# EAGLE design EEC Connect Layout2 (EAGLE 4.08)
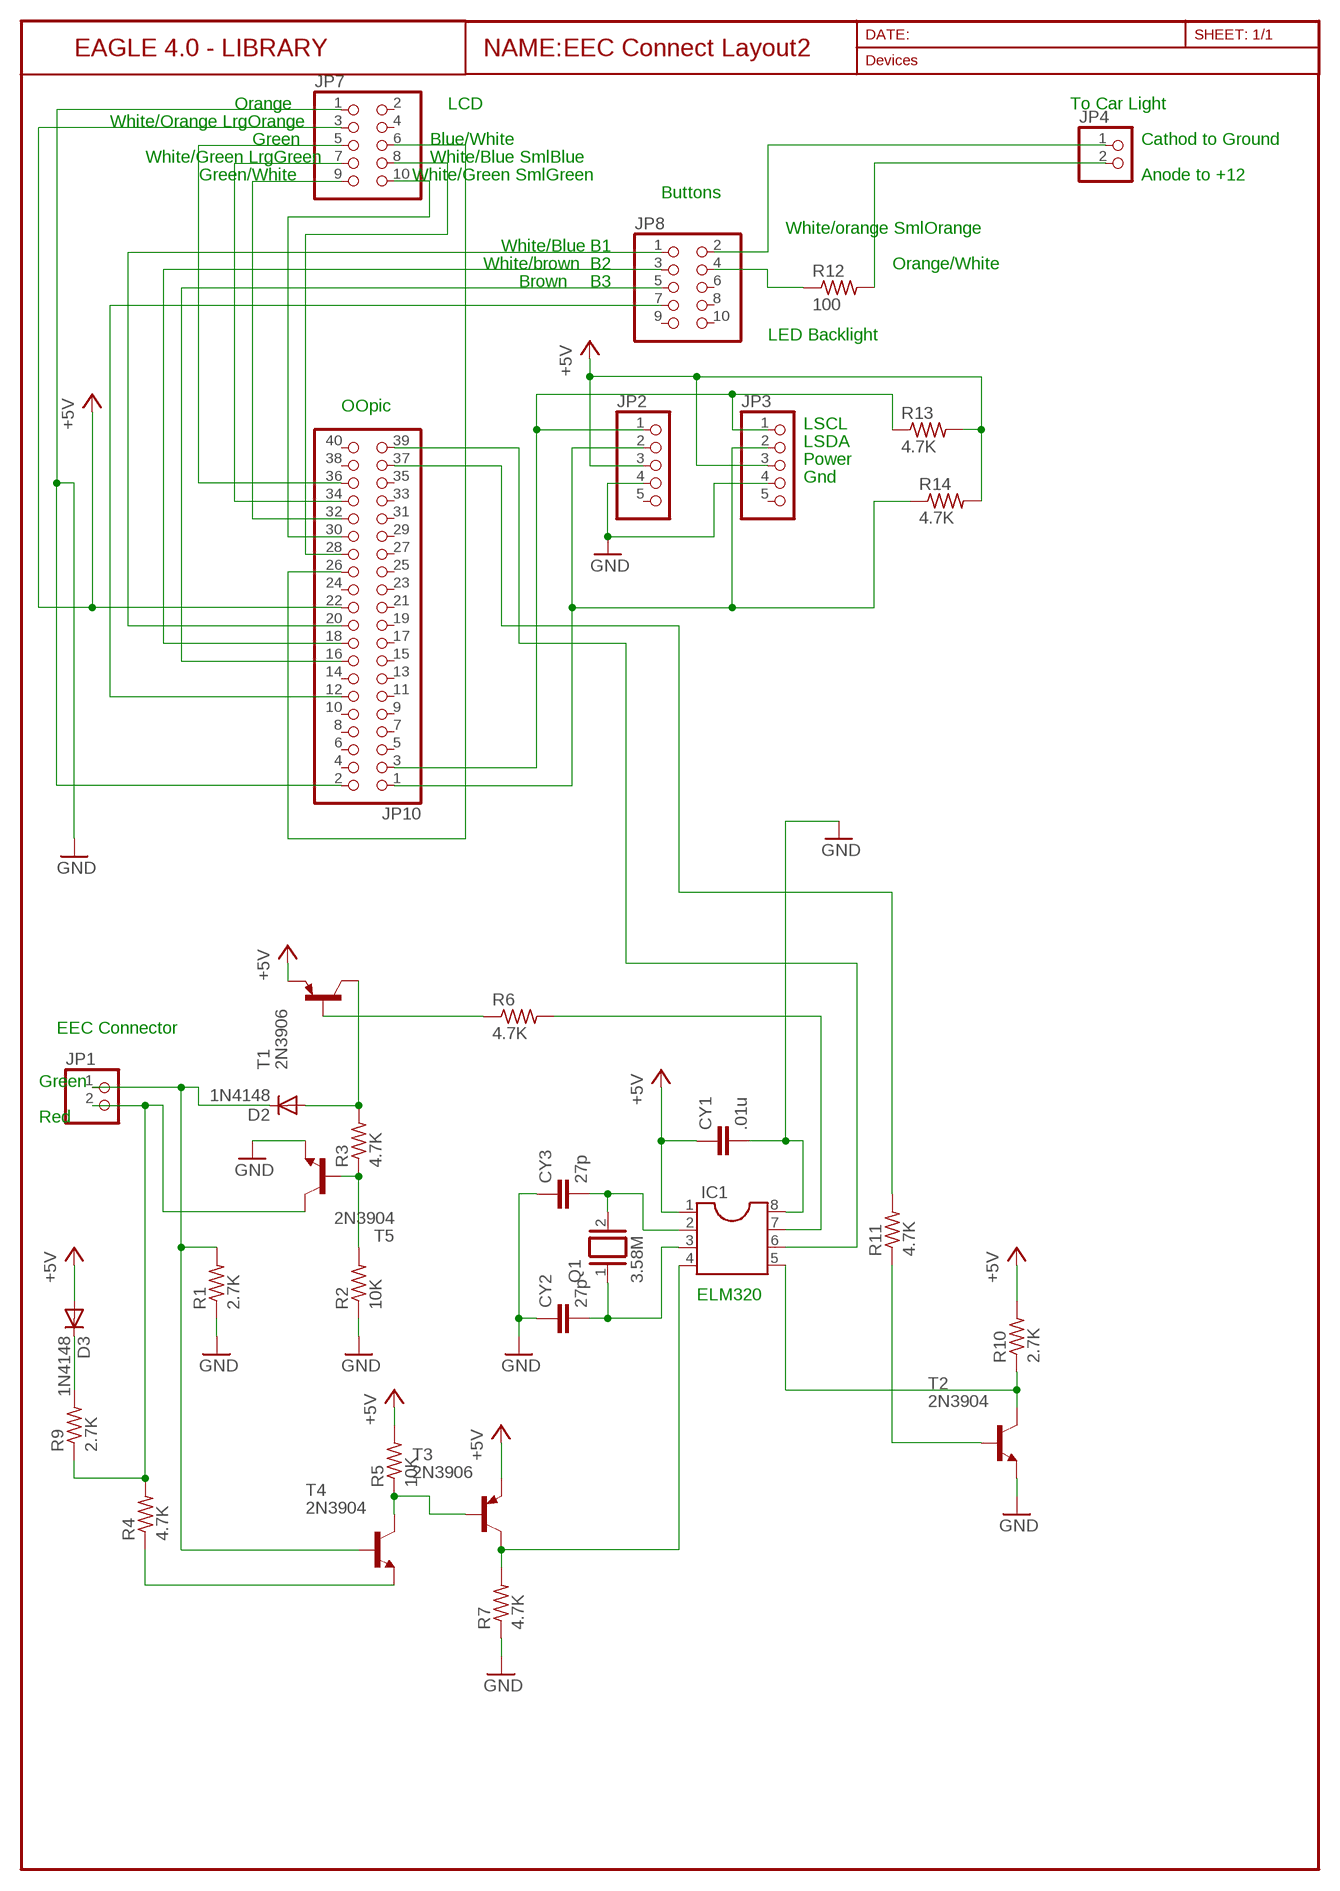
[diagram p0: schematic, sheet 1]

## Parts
CY1  .01u  CYYC7B5  [YC7B5]
CY2  27p  CYYC7B5  [YC7B5]
CY3  27p  CYYC7B5  [YC7B5]
D2  1N4148  [DO35-10]
D3  1N4148  [DO35-10]
IC1  DIL8  [DIL08]
JP1  PINHD-1X2  [1X02]
JP2  PINHD-1X5  [1X05]
JP3  PINHD-1X5  [1X05]
JP4  PINHD-1X2  [1X02]
JP7  PINHD-2X5  [2X05]
JP8  PINHD-2X5  [2X05]
JP10  PINHD-2X20  [2X20]
Q1  3.58M  XTAL/S  [QS]
R1  2.7K  R-US_0207/10  [0207/10]
R2  10K  R-US_0207/10  [0207/10]
R3  4.7K  R-US_0207/10  [0207/10]
R4  4.7K  R-US_0207/10  [0207/10]
R5  10K  R-US_0207/10  [0207/10]
R6  4.7K  R-US_0207/10  [0207/10]
R7  4.7K  R-US_0207/10  [0207/10]
R9  2.7K  R-US_0207/10  [0207/10]
R10  2.7K  R-US_0207/10  [0207/10]
R11  4.7K  R-US_0207/10  [0207/10]
R12  100  R-US_0204/7  [0204/7]
R13  4.7K  R-US_0204/7  [0204/7]
R14  4.7K  R-US_0204/7  [0204/7]
T1  2N3906  [TO92]
T2  2N3904  [TO92]
T3  2N3906  [TO92]
T4  2N3904  [TO92]
T5  2N3904  [TO92]

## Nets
+5V: CY1.1 D3.A IC1.1 JP2.3 JP3.3 JP7.3 JP10.22 R5.2 R10.2 R13.2 R14.2 T1.3(E) T3.3(E)
N$1: JP7.8 JP10.28
N$2: R2.2 R3.1 T5.2(B)
N$3: D2.C JP1.1 R1.2 T4.2(B)
N$4: IC1.4 R7.2 T3.1(C)
N$5: CY3.2 IC1.2 Q1.2
N$6: CY2.2 IC1.3 Q1.1
N$8: JP8.5 JP10.16
N$9: D3.C R9.2
N$10: R4.1 T4.3(E)
N$11: R5.1 T3.2(B) T4.1(C)
N$12: JP7.5 JP10.36
N$13: JP4.2 R12.2
N$15: IC1.7 R6.2
N$16: R6.1 T1.2(B)
N$17: D2.A R3.2 T1.1(C)
N$19: JP1.2 R4.2 R9.1 T5.1(C)
N$20: JP8.4 R12.1
N$21: IC1.6 JP10.39
N$22: JP7.10 JP10.30
N$23: JP4.1 JP8.2
N$24: JP2.1 JP3.1 JP10.3 R13.1
N$25: JP2.2 JP3.2 JP10.1 R14.1
N$26: JP7.6 JP10.26
N$27: JP8.7 JP10.12
N$30: JP8.1 JP10.20
N$31: JP8.3 JP10.18
N$32: CY1.2 CY2.1 CY3.1 IC1.8 JP2.4 JP3.4 JP7.1 JP10.2 R1.1 R2.1 R7.1 T2.3(E) T5.3(E) ; supply symbol labelled GND
N$34: JP7.9 JP10.32
N$35: JP7.7 JP10.34
N$36: R11.1 T2.2(B)
N$37: JP10.37 R11.2
N$40: IC1.5 R10.1 T2.1(C)
Unconnected: JP2.5 JP3.5 JP7.2 JP7.4 JP8.6 JP8.8 JP8.9 JP8.10 JP10.4 JP10.5 JP10.6 JP10.7 JP10.8 JP10.9 JP10.10 JP10.11 JP10.13 JP10.14 JP10.15 JP10.17 JP10.19 JP10.21 JP10.23 JP10.24 JP10.25 JP10.27 JP10.29 JP10.31 JP10.33 JP10.35 JP10.38 JP10.40

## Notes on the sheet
- Orange | LCD | To Car Light
- White/Orange LrgOrange
- Green | Blue/White | Cathod to Ground
- White/Green LrgGreen | White/Blue SmlBlue
- Green/White | White/Green SmlGreen | Anode to +12
- Buttons
- White/orange SmlOrange
- White/Blue | B1
- White/brown | B2 | Orange/White
- Brown | B3
- LED Backlight
- OOpic
- LSCL
- LSDA
- Power
- Gnd
- EEC Connector
- Green
- Red
- ELM320

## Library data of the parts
CY1-CY3 = rcl:CY: Y CAPACITOR
D2 D3 = diode:1N4148: DIODE
IC1 = dil:DIL8: SOCKET Dual In Line
JP1 JP4 = pinhead:PINHD-1X2: PIN HEADER
JP2 JP3 = pinhead:PINHD-1X5: PIN HEADER
JP7 JP8 = pinhead:PINHD-2X5: PIN HEADER
JP10 = pinhead:PINHD-2X20: PIN HEADER
Q1 = special:XTAL/S: CRYSTAL
R1-R7 R9-R14 = rcl:R-US_: RESISTOR, American symbol
T1 T3 = transistor-pnp:2N3906: PNP TRANSISTOR
T2 T4 T5 = transistor-npn:2N3904: NPN TRANSISTOR

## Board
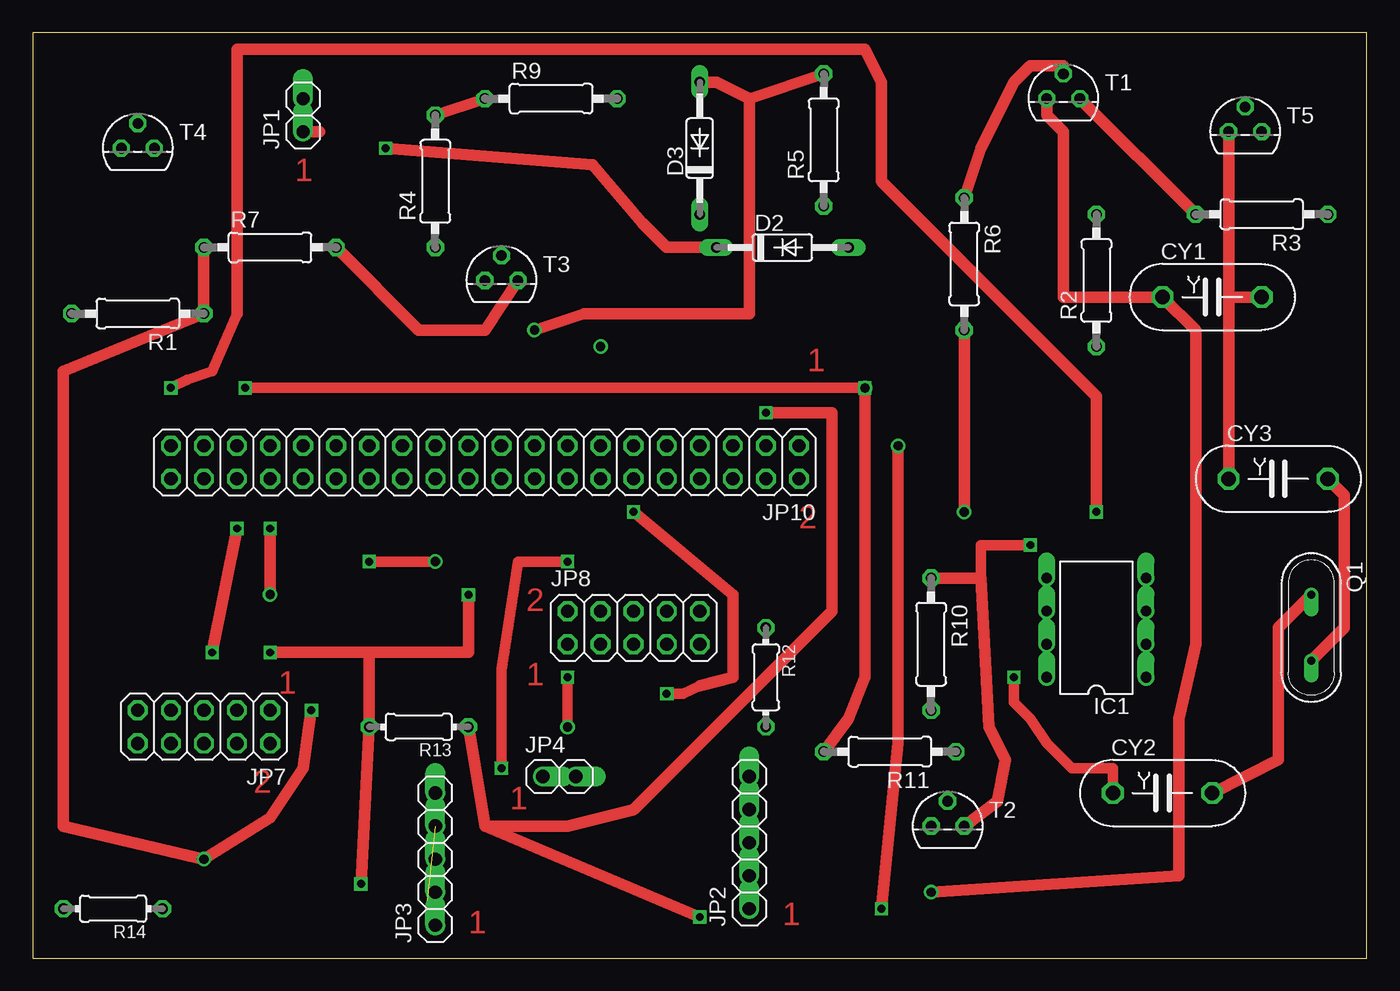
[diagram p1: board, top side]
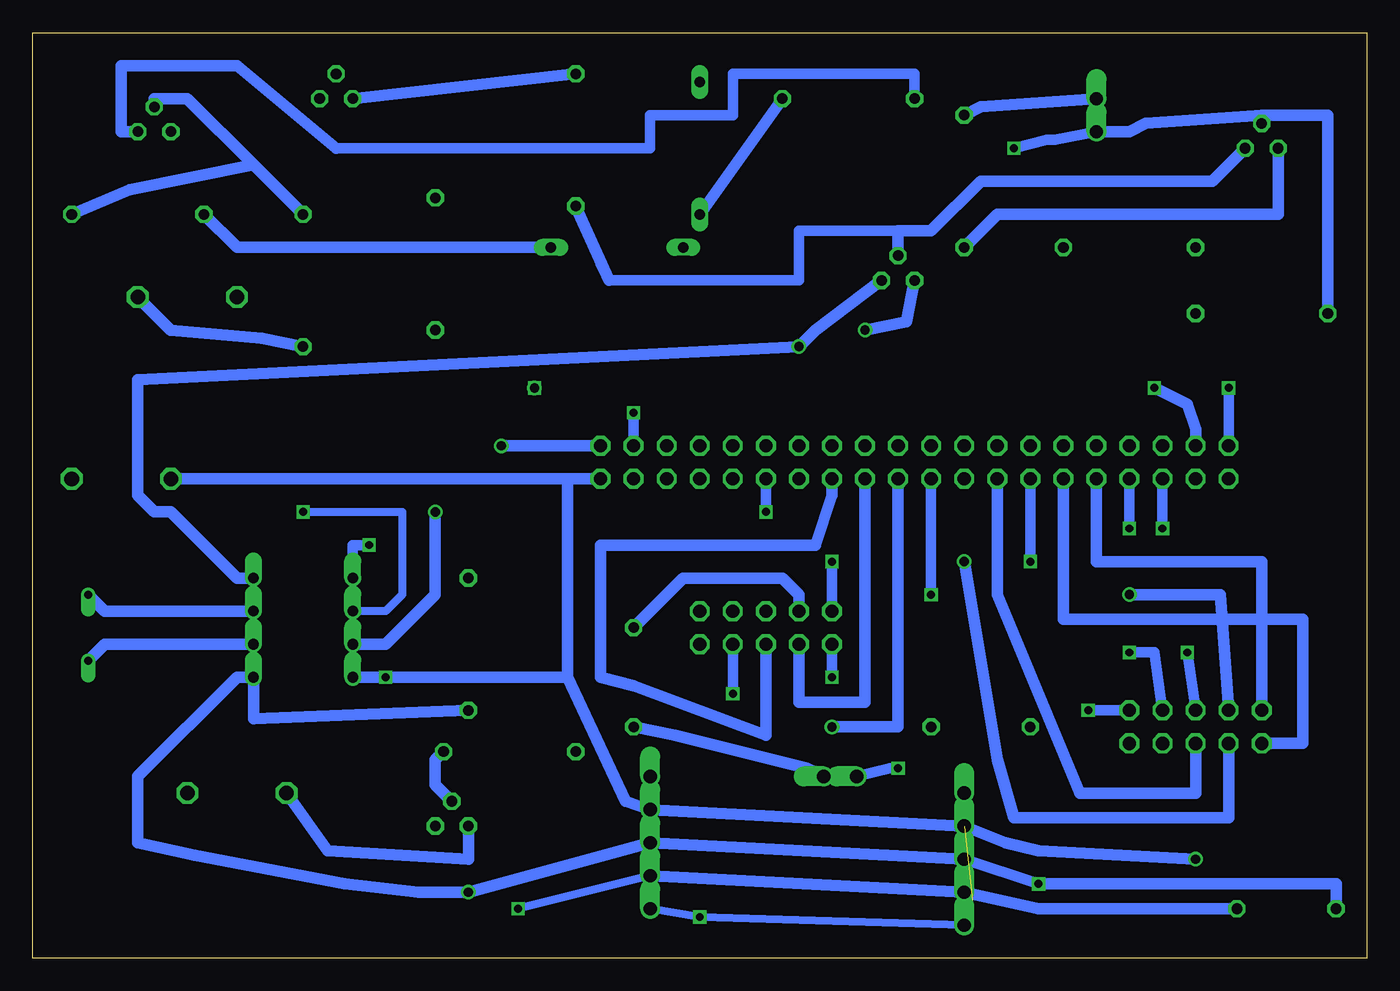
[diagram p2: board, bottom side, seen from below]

Size 102.54 x 71.11 mm. Coordinates in mm from the lower left corner, seen from the top.
Outline: 0,0 102.54,0 102.54,71.11 0,71.11 0,0
Copper layers used: Top, Bottom

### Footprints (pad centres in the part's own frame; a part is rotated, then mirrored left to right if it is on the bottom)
YC7B5 = drill 1.118 octagon: 1 -3.81,0; 2 3.81,0
DO35-10 = drill 0.813 long: A 5.08,0; C -5.08,0
DIL08 = drill 0.813 offset: 1 -3.81,-3.81; 2 -1.27,-3.81; 3 1.27,-3.81; 4 3.81,-3.81; 5 3.81,3.81; 6 1.27,3.81; 7 -1.27,3.81; 8 -3.81,3.81
1X02 = drill 1.016 offset: 1 -1.27,0; 2 1.27,0
1X05 = drill 1.016 offset: 1 -5.08,0; 2 -2.54,0; 3 0,0; 4 2.54,0; 5 5.08,0
2X05 = drill 1.016 octagon: 1 -5.08,-1.27; 2 -5.08,1.27; 3 -2.54,-1.27; 4 -2.54,1.27; 5 0,-1.27; 6 0,1.27; 7 2.54,-1.27; 8 2.54,1.27; 9 5.08,-1.27; 10 5.08,1.27
2X20 = drill 1.016 octagon: 1 -24.13,-1.27; 2 -24.13,1.27; 3 -21.59,-1.27; 4 -21.59,1.27; 5 -19.05,-1.27; 6 -19.05,1.27; 7 -16.51,-1.27; 8 -16.51,1.27; 9 -13.97,-1.27; 10 -13.97,1.27; 11 -11.43,-1.27; 12 -11.43,1.27; 13 -8.89,-1.27; 14 -8.89,1.27; 15 -6.35,-1.27; 16 -6.35,1.27; 17 -3.81,-1.27; 18 -3.81,1.27; 19 -1.27,-1.27; 20 -1.27,1.27; 21 1.27,-1.27; 22 1.27,1.27; 23 3.81,-1.27; 24 3.81,1.27; 25 6.35,-1.27; 26 6.35,1.27; 27 8.89,-1.27; 28 8.89,1.27; 29 11.43,-1.27; 30 11.43,1.27; 31 13.97,-1.27; 32 13.97,1.27; 33 16.51,-1.27; 34 16.51,1.27; 35 19.05,-1.27; 36 19.05,1.27; 37 21.59,-1.27; 38 21.59,1.27; 39 24.13,-1.27; 40 24.13,1.27
QS = drill 0.61 offset: 1 -2.54,0; 2 2.54,0
0207/10 = drill 0.813 octagon: 1 -5.08,0; 2 5.08,0
0204/7 = drill 0.813 octagon: 1 -3.81,0; 2 3.81,0
TO92 = drill 0.813 octagon: 1 1.27,0; 2 0,1.905; 3 -1.27,0

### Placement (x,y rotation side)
CY1  90.64,50.8 0 top
CY2  86.83,12.7 0 top
CY3  95.72,36.82 0 top
D2  57.62,54.6 0 top
D3  51.27,62.23 90 top
IC1  81.75,25.39 90 top
JP1  20.79,64.77 90 top
JP2  55.08,8.89 90 top
JP3  30.95,7.61 90 top
JP4  40.48,13.96 0 top
JP7  13.17,17.77 180 top
JP8  46.19,25.39 0 top
JP10  34.76,38.09 180 top
Q1  98.26,25.39 270 top
R1  8.09,49.52 180 top
R2  81.75,52.06 90 top
R3  94.45,57.14 180 top
R4  30.95,59.68 90 top
R5  60.8,62.86 90 top
R6  71.59,53.34 270 top
R7  18.25,54.6 0 top
R9  39.84,66.04 0 top
R10  69.05,24.12 270 top
R11  65.88,15.87 180 top
R12  56.35,21.59 270 top
R13  29.68,17.77 180 top
R14  6.19,3.81 180 top
T1  79.21,66.04 0 top
T2  70.32,10.16 0 top
T3  36.03,52.06 0 top
T4  8.09,62.23 0 top
T5  93.18,63.49 0 top

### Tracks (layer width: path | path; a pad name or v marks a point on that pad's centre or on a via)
+5V  (via drill 0.61, 0.71)
  Top 0.889: 25.87,23.49 R13.2 v25.23,5.71 | v33.49,27.94 33.49,23.49 25.87,23.49 | 25.87,23.49 v18.25,23.49 | v38.57,48.26 42.38,49.52 55.08,49.52 55.08,66.04 | 55.08,66.04 52.54,67.31 D3.A | R5.2 55.08,66.04 | T1.3 77.94,64.77 79.21,63.49 79.21,50.8 CY1.1 89.37,48.26 89.37,24.12 88.1,18.41 88.1,6.34 v69.05,5.08
  Bottom 0.813: v33.49,27.94 JP10.22 | JP7.3 16.34,23.49 v18.25,23.49
  Bottom 0.889: R14.2 2.38,5.71 v25.23,5.71 JP3.3 JP2.3 v69.05,5.08 72.86,5.08 78.57,5.71 90.09,7.93 94.45,8.89 94.45,13.96 86.83,21.59 IC1.1 85.56,18.41 R10.2 | T3.3 35.4,48.89 v38.57,48.26 | T1.3 R5.2
N$1  (via drill 0.61, 0.71)
  Top 0.813: v30.95,30.48 v25.87,30.48
  Bottom 0.813: v25.87,30.48 JP10.28
  Bottom 0.889: JP7.8 10.63,10.79 27.14,10.79 28.41,15.23 v30.95,30.48
N$2
  Bottom 0.889: 85.56,60.96 90.64,66.04 93.18,66.04 T5.2 | R2.2 85.56,60.96 | R3.1 95.08,59.05 85.56,60.96
N$3  (via drill 0.61)
  Top 0.889: v27.14,62.23 43.02,60.96 46.83,56.51 48.73,54.6 D2.C | JP1.1 22.06,63.49
  Bottom 0.813: v27.14,62.23 24.6,62.86 23.96,62.86 JP1.1
  Bottom 0.889: R1.2 3.01,64.77 8.09,64.77 | 8.09,64.77 16.98,64.13 18.25,63.49 JP1.1 | 8.09,64.77 T4.2
N$4  (via drill 0.71)
  Top 0.889: R7.2 29.68,48.26 34.76,48.26 T3.1
  Bottom 0.889: T3.1 42.38,48.26 v43.65,46.98 94.45,44.45 94.45,35.55 93.18,34.28 91.91,34.28 86.83,29.2 IC1.4
N$5
  Top 0.889: CY3.2 100.8,35.55 100.8,25.39 Q1.2
  Bottom 0.889: Q1.2 96.99,24.12 IC1.2
N$6
  Top 0.889: CY2.2 95.72,15.23 95.72,25.39 Q1.1
  Bottom 0.889: Q1.1 96.99,26.66 IC1.3
N$8
  Bottom 0.889: JP8.5 46.19,17.14 56.35,20.95 58.89,21.59 58.89,31.74 42.38,31.74 41.11,35.55 JP10.16
N$9
  Bottom 0.889: D3.C R9.2
N$10
  Bottom 0.889: T4.3 6.82,57.14 28.41,57.14 R4.1
N$11
  Bottom 0.813: 58.89,53.34 58.26,52.06 43.65,52.06 43.65,55.88 36.03,55.88
  Bottom 0.889: T4.1 11.9,59.68 29.68,59.68 33.49,55.88 36.03,55.88 T3.2 | 58.26,52.06 R5.1
N$12  (via drill 0.61)
  Top 0.889: v13.8,23.49 v15.71,33.02
  Bottom 0.813: v15.71,33.02 JP10.36 | JP7.5 v13.8,23.49
N$13
  Bottom 0.889: R12.2 53.18,17.14 43.02,14.6 JP4.2
N$15  (via drill 0.71)
  Top 0.889: v71.59,34.28 R6.2
  Bottom 0.889: v71.59,34.28 71.59,27.94 75.4,24.12 IC1.7
N$16
  Top 0.889: R6.1 72.86,62.23 75.4,67.31 76.67,68.58 79.21,68.58 T1.2
N$17
  Top 0.889: R3.2 T1.1
  Bottom 0.889: R3.2 86.83,54.6 D2.A
N$19
  Top 0.889: R4.2 R9.1
  Bottom 0.813: 79.21,62.23 55.08,62.23 55.08,64.77 48.73,64.77 48.73,67.94 34.76,67.94 R9.1
  Bottom 0.889: R4.2 29.68,65.4 JP1.2 | T5.1 95.72,63.49 95.72,68.58 86.83,68.58 79.21,62.23
N$20
  Bottom 0.889: R12.1 52.54,29.2 44.92,29.2 43.65,27.94 JP8.4
N$21  (via drill 0.61)
  Top 0.813: v10.63,43.81 11.9,44.45 13.8,45.08 15.71,49.52
  Top 0.889: v81.75,34.28 81.75,43.17 65.24,59.68 65.24,67.31 63.97,69.85 15.71,69.85 15.71,49.52
  Bottom 0.61: v81.75,34.28 74.13,34.28 74.13,27.94 75.4,26.66 IC1.6
  Bottom 0.813: JP10.39 v10.63,43.81
N$22
  Bottom 0.889: JP7.10 4.92,16.5 4.92,26.03 23.33,26.03 JP10.30
N$23  (via drill 0.61)
  Top 0.813: v41.11,30.48 37.3,30.48 36.03,22.22 v36.03,14.6
  Bottom 0.813: v41.11,30.48 JP8.2 | v36.03,14.6 36.66,14.6 JP4.1
N$24  (via drill 0.61)
  Top 0.889: 34.76,10.16 R13.1 | v51.27,3.17 34.76,10.16 | v56.35,41.91 61.43,41.91 61.43,26.66 46.19,11.43 41.11,10.16 34.76,10.16
  Bottom 0.61: JP3.1 v51.27,3.17 JP2.1
  Bottom 0.813: v56.35,41.91 JP10.3
N$25  (via drill 0.61, 0.71)
  Top 0.889: v66.51,39.37 66.51,16.5 v65.24,3.81
  Bottom 0.61: JP2.2 v65.24,3.81
  Bottom 0.889: R14.1 25.23,3.81 JP3.2 JP2.2 | v66.51,39.37 JP10.1
N$26
  Bottom 0.889: JP7.6 13.17,12.7 22.06,12.7 28.41,27.94 JP10.26
N$27  (via drill 0.61)
  Top 0.813: v48.73,20.31 50,20.31 51.27,20.95
  Top 0.889: 51.27,20.95 53.81,21.59 53.81,27.94 v46.19,34.28
  Bottom 0.813: v46.19,34.28 JP10.12 | v48.73,20.31 JP8.7
N$30  (via drill 0.61, 0.71)
  Top 0.813: v41.11,17.77 v41.11,21.59
  Bottom 0.813: v41.11,21.59 JP8.1
  Bottom 0.889: JP10.20 36.03,17.77 v41.11,17.77
N$31
  Bottom 0.889: JP10.18 38.57,19.68 43.65,19.68 JP8.3
N$32  (via drill 0.61, 0.71)  (1 unrouted)
  Top 0.813: v75.4,21.59 75.4,19.68 76.67,18.41 77.94,16.5 79.84,14.6 83.02,14.6 CY2.1
  Top 0.889: R7.1 R1.1 2.38,45.08 2.38,10.16 v13.17,7.61 18.25,10.79 20.79,14.6 v21.42,19.04 | CY3.1 91.91,50.8 | 91.91,50.8 T5.3 | 91.91,50.8 CY1.2
  Bottom 0.813: v21.42,19.04 JP7.1
  Bottom 0.889: R2.1 84.92,47.62 91.91,48.26 CY1.2 | T2.3 69.05,7.61 79.84,8.25 CY2.1 | 61.43,36.82 JP10.2 | 61.43,36.82 CY3.1 | 61.43,21.59 61.43,36.82 | 61.43,21.59 56.98,12.06 JP2.4 JP3.4 27.77,8.89 25.23,8.25 v13.17,7.61 | 61.43,21.59 v75.4,21.59 IC1.8
N$34
  Bottom 0.889: JP7.9 8.09,30.48 20.79,30.48 JP10.32
N$35  (via drill 0.61, 0.71)
  Top 0.889: v18.25,27.94 v18.25,33.02
  Bottom 0.813: v18.25,33.02 JP10.34
  Bottom 0.889: JP7.7 11.27,27.94 v18.25,27.94
N$36
  Bottom 0.889: R11.1 71.59,15.23 71.59,13.33 T2.2
N$37  (via drill 0.61, 0.71)
  Top 0.813: v16.34,43.81 v63.97,43.81
  Top 0.889: R11.2 62.7,18.41 63.97,21.59 v63.97,43.81
  Bottom 0.889: v16.34,43.81 13.8,42.54 13.17,40.63 JP10.37
N$40  (via drill 0.61)
  Top 0.813: 72.86,29.2 72.86,31.74 v76.67,31.74
  Top 0.889: T2.1 74.13,12.06 74.77,15.23 73.49,17.77 72.86,29.2 R10.1
  Bottom 0.813: v76.67,31.74 77.94,31.74 IC1.5

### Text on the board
Top: 1 | 1 | 2 | 2 | 1 | 1 | 2 | 1 | 1 | 1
